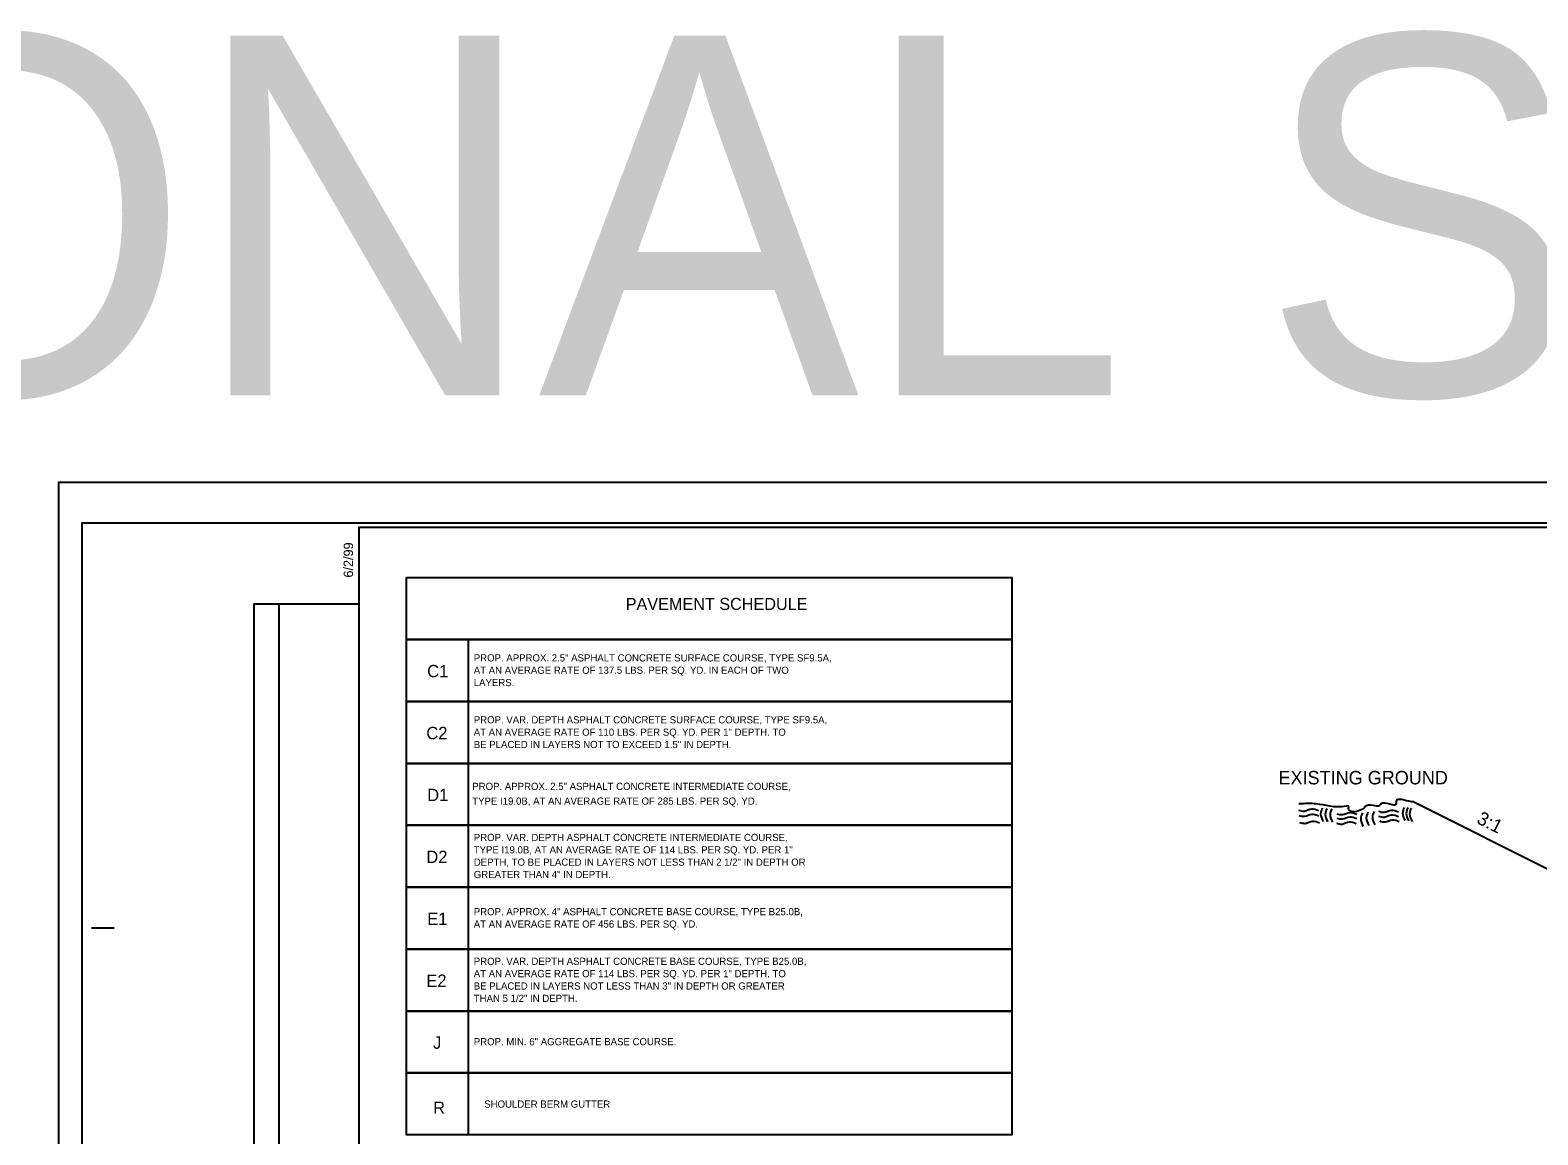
# Model space of a CAD drawing. Extents: x 575722 to 576066, y -53107 to -52774.
# Drawn here: x 575795 to 575878.8, y -52835 to -52773.6 of the extents above; entities that cross this region are included whole.
import ezdxf

# ---------------------------------------------------------------- set-up
doc = ezdxf.new("R2010")
doc.units = 0
for name, color, linetype in [('Old_Level_19', 7, 'Continuous'), ('Old_Level_2', 7, 'Continuous'), ('Prop Pavement Schedule Description CELL', 7, 'Continuous'), ('Sheet Block Revision CELL', 7, 'Continuous'), ('Sheet Cutting Line CELL', 7, 'Continuous'), ('Sheet Plot Border Inside CELL', 7, 'Continuous'), ('Sheet Plot Border Outside CELL', 7, 'Continuous'), ('Sheet Typical CELL', 7, 'Continuous'), ('Typical Pavement Slope CELL', 7, 'Continuous'), ('Typical Slope Point Local CELL', 7, 'Continuous'), ('Typical Text Grade Point CELL', 7, 'Continuous')]:
    doc.layers.add(name, color=color, linetype=linetype)

msp = doc.modelspace()

# ---------------------------------------------------------------- linework, layer by layer
at = {"layer": 'Old_Level_19'}
msp.add_lwpolyline([(575819.369, -52835.019), (575815.934, -52835.019), (575815.934, -52831.584), (575849.594, -52831.584), (575849.594, -52835.019), (575819.369, -52835.019), (575819.369, -52831.584)], dxfattribs=at)
at = {"layer": 'Old_Level_2'}
for points in [[(575871.929, -52816.517), (575871.787, -52816.502), (575870.947, -52816.502), (575870.947, -52816.622), (575870.107, -52816.622), (575869.987, -52816.742), (575869.867, -52816.742), (575869.267, -52816.742), (575869.147, -52816.862), (575868.307, -52816.862), (575868.307, -52816.742), (575868.187, -52816.742), (575866.507, -52816.622), (575865.55, -52816.622)], [(575866.639, -52817.01), (575866.249, -52816.916), (575865.846, -52817.037), (575865.55, -52816.983)], [(575866.652, -52817.306), (575866.262, -52817.211), (575865.859, -52817.332), (575865.563, -52817.279)], [(575866.847, -52816.855), (575866.753, -52817.178), (575866.888, -52817.594)], [(575867.103, -52816.882), (575867.008, -52817.205), (575867.143, -52817.621)], [(575867.371, -52816.895), (575867.277, -52817.218), (575867.412, -52817.635)], [(575868.762, -52817.211), (575868.373, -52817.117), (575867.969, -52817.238), (575867.674, -52817.185)], [(575868.762, -52817.453), (575868.373, -52817.359), (575867.969, -52817.48), (575867.674, -52817.426)], [(575869.078, -52817.124), (575868.984, -52817.447), (575869.119, -52817.863)], [(575869.387, -52817.084), (575869.293, -52817.406), (575869.428, -52817.823)], [(575869.723, -52817.043), (575869.629, -52817.366), (575869.764, -52817.783)], [(575871.074, -52817.077), (575870.684, -52816.983), (575870.281, -52817.104), (575869.985, -52817.05)], [(575871.088, -52817.346), (575870.698, -52817.252), (575870.295, -52817.373), (575869.999, -52817.319)], [(575871.128, -52817.615), (575870.738, -52817.521), (575870.335, -52817.642), (575870.039, -52817.588)], [(575871.403, -52816.815), (575871.309, -52817.137), (575871.444, -52817.554)], [(575871.605, -52816.828), (575871.511, -52817.151), (575871.645, -52817.568)], [(575871.793, -52816.855), (575871.699, -52817.178), (575871.834, -52817.594)], [(575866.692, -52817.695), (575866.303, -52817.601), (575865.899, -52817.722), (575865.604, -52817.668)], [(575868.735, -52817.736), (575868.346, -52817.642), (575867.942, -52817.762), (575867.647, -52817.709)]]:
    msp.add_spline(points, degree=3, dxfattribs=at)
at = {"layer": 'Prop Pavement Schedule Description CELL'}
msp.add_lwpolyline([(575815.934, -52804.044), (575849.594, -52804.044), (575849.594, -52807.486), (575815.934, -52807.486)], close=True, dxfattribs=at)
for points in [[(575819.376, -52810.929), (575815.934, -52810.929), (575815.934, -52807.486), (575849.594, -52807.486), (575849.594, -52810.929), (575819.376, -52810.929), (575819.376, -52807.486)], [(575819.376, -52814.372), (575815.934, -52814.372), (575815.934, -52810.929), (575849.594, -52810.929), (575849.594, -52814.372), (575819.376, -52814.372), (575819.376, -52810.929)], [(575819.376, -52817.814), (575815.934, -52817.814), (575815.934, -52814.372), (575849.594, -52814.372), (575849.594, -52817.814), (575819.376, -52817.814), (575819.376, -52814.372)], [(575819.376, -52821.257), (575815.934, -52821.257), (575815.934, -52817.814), (575849.594, -52817.814), (575849.594, -52821.257), (575819.376, -52821.257), (575819.376, -52817.814)], [(575819.376, -52824.699), (575815.934, -52824.699), (575815.934, -52821.257), (575849.594, -52821.257), (575849.594, -52824.699), (575819.376, -52824.699), (575819.376, -52821.257)], [(575819.376, -52828.142), (575815.934, -52828.142), (575815.934, -52824.699), (575849.594, -52824.699), (575849.594, -52828.142), (575819.376, -52828.142), (575819.376, -52824.699)], [(575819.376, -52831.584), (575815.934, -52831.584), (575815.934, -52828.142), (575849.594, -52828.142), (575849.594, -52831.584), (575819.376, -52831.584), (575819.376, -52828.142)]]:
    msp.add_lwpolyline(points, dxfattribs=at)
at = {"layer": 'Sheet Block Revision CELL'}
msp.add_line((575808.859, -52881.41), (575808.859, -52805.507), dxfattribs=at)
msp.add_lwpolyline([(575807.462, -52881.41), (575807.462, -52805.507), (575813.275, -52805.507), (575813.275, -52881.41)], close=True, dxfattribs=at)
at = {"layer": 'Sheet Cutting Line CELL'}
for p, q in [((575964.975, -52798.762), (575796.575, -52798.762)), ((575796.575, -52798.762), (575796.575, -52908.762))]:
    msp.add_line(p, q, dxfattribs=at)
at = {"layer": 'Sheet Plot Border Inside CELL'}
msp.add_lwpolyline([(575964.525, -52801.007), (575797.875, -52801.007), (575797.875, -52906.517), (575964.525, -52906.517)], close=True, dxfattribs=at)
at = {"layer": 'Sheet Plot Border Outside CELL'}
msp.add_lwpolyline([(575964.975, -52798.762), (575796.575, -52798.762), (575796.575, -52908.762), (575964.975, -52908.762)], close=True, dxfattribs=at)
at = {"layer": 'Sheet Typical CELL'}
msp.add_line((575798.425, -52823.512), (575799.675, -52823.512), dxfattribs=at)
msp.add_lwpolyline([(575963.275, -52801.262), (575813.275, -52801.262), (575813.275, -52906.262), (575963.275, -52906.262)], close=True, dxfattribs=at)
at = {"layer": 'Typical Slope Point Local CELL'}
msp.add_line((575871.929, -52816.517), (575879.858, -52820.482), dxfattribs=at)

# ---------------------------------------------------------------- texts
at = {"layer": 'Prop Pavement Schedule Description CELL'}
for s, height, p in [('PAVEMENT SCHEDULE', 0.6732, (575828.119, -52805.843)), ('C1', 0.6872, (575817.081, -52809.583)), ('AT AN AVERAGE RATE OF 137.5 LBS. PER SQ. YD. IN EACH OF TWO ', 0.3995, (575819.67, -52809.39)), ('PROP. APPROX. 2.5" ASPHALT CONCRETE SURFACE COURSE, TYPE SF9.5A, ', 0.3995, (575819.67, -52808.704)), ('LAYERS.', 0.3995, (575819.67, -52810.077)), ('C2', 0.6872, (575817.033, -52813.025)), ('AT AN AVERAGE RATE OF 110 LBS. PER SQ. YD. PER 1" DEPTH. TO', 0.3995, (575819.67, -52812.834)), ('PROP. VAR. DEPTH ASPHALT CONCRETE SURFACE COURSE, TYPE SF9.5A,', 0.3995, (575819.67, -52812.147)), ('BE PLACED IN LAYERS NOT TO EXCEED 1.5" IN DEPTH.', 0.3995, (575819.67, -52813.52)), ('D1', 0.6872, (575817.081, -52816.469)), ('PROP. APPROX. 2.5" ASPHALT CONCRETE INTERMEDIATE COURSE,', 0.3995, (575819.586, -52815.848)), ('TYPE I19.0B, AT AN AVERAGE RATE OF 285 LBS. PER SQ. YD.', 0.3995, (575819.586, -52816.667)), ('PROP. VAR. DEPTH ASPHALT CONCRETE INTERMEDIATE COURSE,', 0.3995, (575819.67, -52818.688)), ('TYPE I19.0B, AT AN AVERAGE RATE OF 114 LBS. PER SQ. YD. PER 1" ', 0.3995, (575819.67, -52819.375)), ('D2', 0.6872, (575817.033, -52819.91)), ('DEPTH, TO BE PLACED IN LAYERS NOT LESS THAN 2 1/2" IN DEPTH OR', 0.3995, (575819.67, -52820.061)), ('GREATER THAN 4" IN DEPTH.', 0.3995, (575819.67, -52820.748)), ('PROP. APPROX. 4" ASPHALT CONCRETE BASE COURSE, TYPE B25.0B,', 0.3995, (575819.67, -52822.815)), ('E1', 0.6872, (575817.081, -52823.353)), ('AT AN AVERAGE RATE OF 456 LBS. PER SQ. YD.', 0.3995, (575819.67, -52823.501)), ('AT AN AVERAGE RATE OF 114 LBS. PER SQ. YD. PER 1" DEPTH. TO', 0.3995, (575819.67, -52826.26)), ('PROP. VAR. DEPTH ASPHALT CONCRETE BASE COURSE, TYPE B25.0B,', 0.3995, (575819.67, -52825.573)), ('E2', 0.6872, (575817.033, -52826.796)), ('BE PLACED IN LAYERS NOT LESS THAN 3" IN DEPTH OR GREATER', 0.3995, (575819.67, -52826.946)), ('THAN 5 1/2" IN DEPTH.', 0.3995, (575819.67, -52827.633)), ('J', 0.687, (575817.406, -52830.238)), ('PROP. MIN. 6" AGGREGATE BASE COURSE.', 0.3995, (575819.67, -52830.042)), ('R', 0.673, (575817.421, -52833.849)), ('SHOULDER BERM GUTTER', 0.3995, (575820.253, -52833.512))]:
    msp.add_text(s, height=height, dxfattribs=at).set_placement(p)
at = {"layer": 'Sheet Typical CELL'}
msp.add_text('6/2/99', height=0.525, rotation=90, dxfattribs=at).set_placement((575812.96, -52804.037))
at = {"layer": 'Typical Pavement Slope CELL'}
msp.add_text('OPTIONAL SHEET LAYOUT', height=20, dxfattribs=at).set_placement((575720.738, -52793.902))
at = {"layer": 'Typical Slope Point Local CELL'}
msp.add_text('3:1', height=0.75, rotation=333.43495, dxfattribs=at).set_placement((575875.38, -52817.669))
at = {"layer": 'Typical Text Grade Point CELL'}
msp.add_text('EXISTING GROUND', height=0.75, dxfattribs=at).set_placement((575864.411, -52815.538))

doc.saveas('drawing.dxf')
